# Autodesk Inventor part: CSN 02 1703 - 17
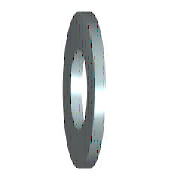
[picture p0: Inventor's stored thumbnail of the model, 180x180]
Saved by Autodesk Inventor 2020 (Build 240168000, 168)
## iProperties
Created: 2019-01
Part Number: CSN 02 1703 - 17
Material: Ocel, měkká
Description: Podložky pro šrouby s válcovou a půlkulovou hlavou
Document SubType Name: Modeling
Standard: CSN 02 1703
Designer: doma
Standards Organization: CSN
Language: cs-CZ
Size Designation: 17
Categories: <MemberInstance><Categories><Category DisplayName="Spojovací materiál" InternalName="e4da775c-781d-43d5-af7c-5136215cf5a6" Mnemonic="FSTN"><Category DisplayName
Density: 7.85 g/cm^3
Appearance: Pololeštěná
IsCustomPart: 0
Author: doma
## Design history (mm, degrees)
sketch "Náčrt"
  geometry: C1 r 13.5 at (0, 0); C2 r 8.5 at (0, 0); 1 further point
  constraints: 2 centre point, 2 coincident
  dimensions: "d0" = 17 diameter of C2 (= SD1); "d1" = 27 diameter of C1 (= SD2)
extrude "Těleso" new body sketch "Náčrt" distance "d2" = 3 (= SD); taper "d3" = 0 deg
workaxis "Work Axis1"
workplane "Work Plane1"
body "Solid1"
other parameters: "SD1" = 17 [user parameter; used in 1 equation term], "SD2" = 27 [user parameter; used in 1 equation term], "SD" = 3 [user parameter; used in 1 equation term], "d4" = 0, "d5" = 0, "d6" = 0, "d7" = 0, "NND" = 16 [user parameter]
